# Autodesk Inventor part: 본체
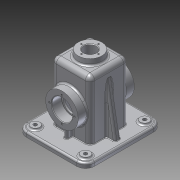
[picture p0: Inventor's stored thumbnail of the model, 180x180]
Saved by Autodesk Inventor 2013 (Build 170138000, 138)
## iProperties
Created: 2016-01
Part Number: 본체
Material: 알루미늄 6061
Document SubType Name: Modeling
Designer: User
Density: 2.71 g/cm^3
Mass: 774.955 g
Surface Area: 900.619 cm^2
Volume: 285.961 cm^3
Author: User
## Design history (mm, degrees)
sketch "스케치1"
  geometry: L1 (-32.5, 32.5)-(32.5, 32.5); L2 (32.5, 32.5)-(32.5, -32.5); L3 (32.5, -32.5)-(-32.5, -32.5); L4 (-32.5, -32.5)-(-32.5, 32.5); 3 further points
  constraints: 8 end point, 2 midpoint, 2 parallel, 1 horizontal, 1 horizontal alignment, 1 perpendicular, 1 vertical alignment
  dimensions: "d0" = 65 distance of L1.start L1.end; "d2" = 65 distance of L1.end L2.end
extrude "돌출1" new body sketch "스케치1" distance "d3" = 100; taper "d4" = 0 deg
sketch "스케치2"
  geometry: L1 (-65, 57.5)-(65, 57.5); L2 (65, 57.5)-(65, -57.5); L3 (65, -57.5)-(-65, -57.5); L4 (-65, -57.5)-(-65, 57.5); 3 further points
  constraints: 8 end point, 2 midpoint, 2 parallel, 1 horizontal, 1 horizontal alignment, 1 perpendicular, 1 vertical alignment
  dimensions: "d5" = 130 distance of L1.start L1.end; "d7" = 115 distance of L1.end L2.end
extrude "돌출2" join sketch "스케치2" distance "d8" = 10; taper "d9" = 0 deg
sketch "스케치3"
  geometry: L1 (65, 57.5)-(-65, 57.5) reference; L2 (-65, 57.5)-(-65, -57.5) reference; L3 (-65, 57.5)-(65, 57.5); L4 (65, 57.5)-(65, -57.5); L5 (65, -57.5)-(-65, -57.5); L6 (-65, -57.5)-(-65, 57.5); L7 (-60, 52.5)-(60, 52.5); L8 (60, 52.5)-(60, -52.5); L9 (60, -52.5)-(-60, -52.5); L10 (-60, -52.5)-(-60, 52.5); 3 further points
  constraints: 16 end point, 4 parallel, 2 horizontal, 2 midpoint, 2 perpendicular, 1 horizontal alignment, 1 vertical alignment
  dimensions: "d10" = 5 distance between parallel lines of L1 L7; "d11" = 5 distance between parallel lines of L10 L2
extrude "돌출3" cut sketch "스케치3" distance "d12" = 2; taper "d13" = 0 deg
sketch "스케치4"
  geometry: L1 (0, 0)-(0, 65) reference; L2 (110, 85)-(110, -20) reference; C1 r 27.5 at (55, 32.5); 2 further points
  constraints: 1 centre point, 1 horizontal alignment, 1 midpoint
  dimensions: "d14" = 55 diameter of C1; "d15" = 55 distance from line of C1.centre L2
extrude "돌출4" join sketch "스케치4" distance "d16" = 15; taper "d17" = 0 deg
sketch "스케치5"
  geometry: C1 r 20 at (0, 0); 1 further point
  constraints: 2 coincident, 1 centre point
  dimensions: "d18" = 40 diameter of C1
extrude "돌출5" join sketch "스케치5" distance "d19" = 10; taper "d20" = 0 deg
sketch "스케치6"
  geometry: L1 (-27.5, 27.5)-(27.5, 27.5); L2 (27.5, 27.5)-(27.5, -27.5); L3 (27.5, -27.5)-(-27.5, -27.5); L4 (-27.5, -27.5)-(-27.5, 27.5); 3 further points
  constraints: 8 end point, 2 midpoint, 2 parallel, 1 horizontal, 1 horizontal alignment, 1 perpendicular, 1 vertical alignment
  dimensions: "d21" = 55 distance of L1.start L1.end; "d23" = 55 distance of L1.end L2.end
extrude "돌출6" cut sketch "스케치6" distance "d24" = 105; taper "d25" = 0 deg
hole "구멍1" diameter "d28" = 21; stored, may be unused: countersink angle "d32" = 90 deg, drill point angle "d34" = 118 deg; dims "d26" = 10, "d27" = 10, "d29" = 6, "d30" = 4, "d31" = 2, "d33" = 8
hole "구멍2" diameter "d37" = 30; stored, may be unused: countersink angle "d41" = 90 deg, drill point angle "d43" = 118 deg; dims "d35" = 10, "d36" = 10, "d38" = 6, "d39" = 4, "d40" = 2, "d42" = 8
hole "구멍3" diameter "d46" = 35; stored, may be unused: countersink angle "d50" = 90 deg, drill point angle "d52" = 0 deg; dims "d44" = 10, "d45" = 10, "d47" = 6, "d48" = 4, "d49" = 2, "d51" = 17
hole "구멍4" diameter "d55" = 35; stored, may be unused: countersink angle "d59" = 90 deg, drill point angle "d61" = 0 deg; dims "d53" = 10, "d54" = 10, "d56" = 6, "d57" = 4, "d58" = 2, "d60" = 17
fillet "모깎기1" dims "d62" = 15
fillet "모깎기2" dims "d63" = 8
fillet "모깎기3" dims "d64" = 3
feature "면 기울기1" dims angle "d65" = 5 deg
fillet "모깎기4" dims "d66" = 3
fillet "모깎기5" dims "d67" = 8
chamfer "모따기2" distance "d71" = 1; stored, may be unused: second distance "d72" = 2, angle "d73" = 45 deg
fillet "모깎기6" dims "d74" = 0.3
fillet "모깎기7" dims "d75" = 3
fillet "모깎기8" dims "d76" = 3
fillet "모깎기9" dims "d77" = 10
sketch "스케치7"
  geometry: C1 r 7.5 at (-50, -42.5); C2 r 7.5 at (-50, 42.5); C3 r 7.5 at (50, 42.5); C4 r 7.5 at (50, -42.5); A1 r 12 centre (50, 42.5) between (62, 42.5) and (50, 54.5) reference; A2 r 12 centre (-50, 42.5) between (-50, 54.5) and (-62, 42.5) reference; A3 r 12 centre (-50, -42.5) between (-62, -42.5) and (-50, -54.5) reference; A4 r 12 centre (50, -42.5) between (50, -54.5) and (62, -42.5) reference; 1 further point
  constraints: 4 centre point, 4 coincident
  dimensions: "d78" = 15 diameter of C1; "d79" = 15 diameter of C2; "d80" = 15 diameter of C3; "d81" = 15 diameter of C4
extrude "돌출7" join sketch "스케치7" distance "d82" = 3; taper "d83" = 0 deg
hole "구멍5" diameter "d86" = 6; stored, may be unused: countersink angle "d90" = 90 deg, drill point angle "d92" = 0 deg; dims "d84" = 10, "d85" = 10, "d87" = 6, "d88" = 4, "d89" = 2, "d91" = 17
hole "구멍6" diameter "d95" = 6; stored, may be unused: countersink angle "d99" = 90 deg, drill point angle "d101" = 0 deg; dims "d93" = 10, "d94" = 10, "d96" = 6, "d97" = 4, "d98" = 2, "d100" = 17
hole "구멍7" diameter "d104" = 6; stored, may be unused: countersink angle "d108" = 90 deg, drill point angle "d110" = 0 deg; dims "d102" = 10, "d103" = 10, "d105" = 6, "d106" = 4, "d107" = 2, "d109" = 17
hole "구멍8" diameter "d113" = 6; stored, may be unused: countersink angle "d117" = 90 deg, drill point angle "d119" = 0 deg; dims "d111" = 10, "d112" = 10, "d114" = 6, "d115" = 4, "d116" = 2, "d118" = 17
fillet "모깎기10" dims "d120" = 3
sketch "스케치8"
  geometry: L1 (-32.5, 8)-(-32.5, 100) reference; L2 (-53, 100)-(-32, 100) reference; L3 (-32.5, 14.931)-(-47.5, 100); L4 (-57.5, 103)-(-57.5, 108) reference; L5 (-47.5, 100)-(-32.5, 100); 1 further point
  constraints: 4 end point, 2 point on line, 1 perpendicular
  dimensions: "d121" = 100 deg angle of L2 L3; "d122" = 10 distance from line of L3.end L4
feature "리브1" sketch "스케치8" dims "d123" = 1, "d124" = 10, "d125" = 0, "d126" = 0, "d127" = 1, "d128" = 1
fillet "모깎기11" dims "d129" = 3
fillet "모깎기12" dims "d130" = 3
fillet "모깎기13" dims "d131" = 3
fillet "모깎기14" dims "d132" = 3
sketch "스케치9"
  geometry: L1 (-60.5, 100)-(-39.5, 100) reference; L2 (-47.5, 82.5)-(-35.5, 82.5) reference; L3 (-42.5, 82.5)-(-42.5, 100); L4 (-27.5, 8)-(-27.5, 110) reference; L5 (-42.5, 100)-(-32.451, 100); 1 further point
  constraints: 4 end point, 2 perpendicular, 2 point on line
  dimensions: "d133" = 15 distance between parallel lines of L3 L4
feature "리브2" sketch "스케치9" dims "d134" = 1, "d135" = 6, "d136" = 0, "d137" = 0, "d138" = 1, "d139" = 1
fillet "모깎기15" dims "d140" = 3
fillet "모깎기17" dims "d142" = 3
fillet "모깎기18" dims "d143" = 3
fillet "모깎기19" dims "d144" = 1
chamfer "모따기3" distance "d145" = 1; stored, may be unused: second distance "d146" = 2, angle "d147" = 45 deg
sketch "스케치10"
  geometry: C1 r 27.5 at (0, 0) reference; 2 further points
  constraints: 1 horizontal alignment
  dimensions: "d148" = 21 distance of C1.centre point (-21, 0)
hole "구멍9" sketch "스케치10" at (-21, 0) diameter "d149" = 3.242; stored, may be unused: countersink angle "d153" = 90 deg, drill point angle "d155" = 118 deg; dims "d150" = 8, "d151" = 4, "d152" = 2, "d154" = 10
sketch "스케치11"
  geometry: C1 r 20 at (0, 0) reference; 1 further point
  constraints: 1 vertical alignment
  dimensions: "d159" = 14.5 distance of C1.centre point (0, 14.5)
hole "구멍10" sketch "스케치11" at (0, 14.5) diameter "d160" = 2.459; stored, may be unused: countersink angle "d164" = 90 deg, drill point angle "d166" = 118 deg; dims "d161" = 7, "d162" = 4, "d163" = 2, "d165" = 9
sketch "스케치12"
  geometry: L1 (47, 32.5)-(-44, 32.5) reference; L2 (65, -20)-(65, 20) reference; 2 further points
  constraints: 1 other
  dimensions: "d170" = 32.5 distance from line of L1 point (39, 0); "d171" = 26 distance from line of L2 point (39, 0)
feature "엠보싱1" sketch "스케치12" dims "d172" = 0.5, "d173" = 0
node "솔리드1"
mirror "대칭1"
mirror "대칭2"
mirror "대칭3"
pattern_circular "원형 패턴1" dims angle "d157" = 360 deg
mirror "대칭4"
pattern_circular "원형 패턴2" dims angle "d168" = 360 deg
